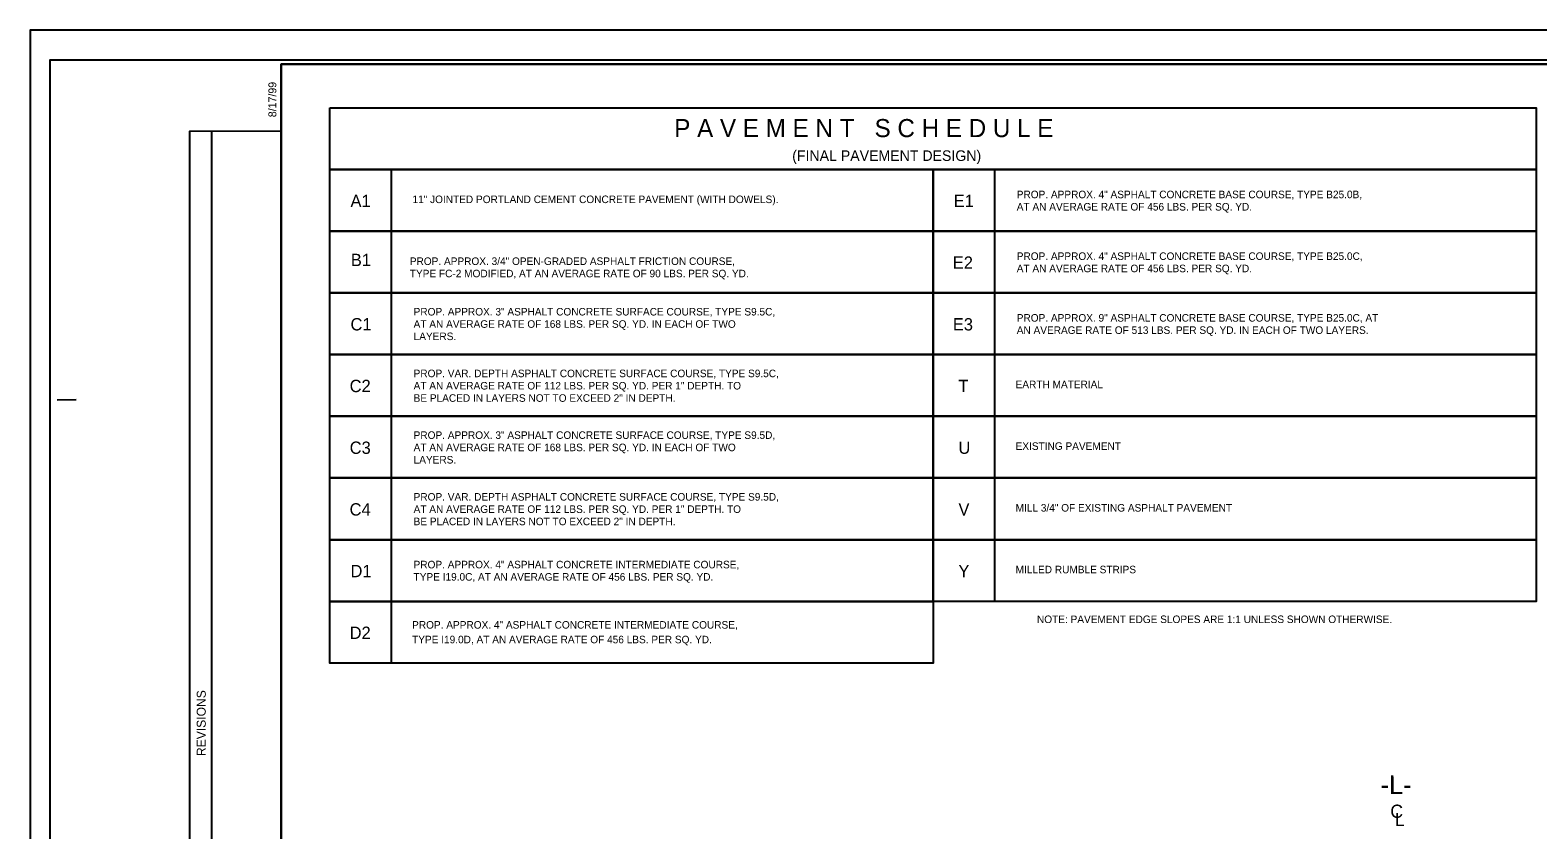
# Model space of a CAD drawing. Extents: x 2241081 to 2251104, y 658534 to 663427.
# Drawn here: x 2247636 to 2248635, y 662384 to 662914 of the extents above; entities that cross this region are included whole.
import ezdxf

# ---------------------------------------------------------------- set-up
doc = ezdxf.new("R2010")
doc.units = 0
for name, color, linetype in [('Prop Dimension Text', 7, 'Continuous'), ('Prop Pavement Schedule Description CELL', 7, 'Continuous'), ('Sheet Block Revision CELL', 7, 'Continuous'), ('Sheet Cutting Line CELL', 7, 'Continuous'), ('Sheet Plan CELL', 7, 'Continuous'), ('Sheet Plot Border Inside CELL', 7, 'Continuous'), ('Sheet Plot Border Outside CELL', 7, 'Continuous'), ('Typical Text Centerline CELL', 7, 'Continuous')]:
    doc.layers.add(name, color=color, linetype=linetype)

msp = doc.modelspace()

# ---------------------------------------------------------------- linework, layer by layer
at = {"layer": 'Prop Pavement Schedule Description CELL'}
msp.add_lwpolyline([(2247834.33, 662862.8), (2248634.35, 662862.8), (2248634.35, 662821.89), (2247834.33, 662821.89)], close=True, dxfattribs=at)
for points in [[(2247875.24, 662780.98), (2247834.33, 662780.98), (2247834.33, 662821.89), (2248234.33, 662821.89), (2248234.33, 662780.98), (2247875.24, 662780.98), (2247875.24, 662821.89)], [(2248275.24, 662780.96), (2248234.33, 662780.96), (2248234.33, 662821.86), (2248634.33, 662821.86), (2248634.33, 662780.96), (2248275.24, 662780.96), (2248275.24, 662821.86)], [(2247875.24, 662740.07), (2247834.33, 662740.07), (2247834.33, 662780.98), (2248234.33, 662780.98), (2248234.33, 662740.07), (2247875.24, 662740.07), (2247875.24, 662780.98)], [(2248275.24, 662740.05), (2248234.33, 662740.05), (2248234.33, 662780.96), (2248634.33, 662780.96), (2248634.33, 662740.05), (2248275.24, 662740.05), (2248275.24, 662780.96)], [(2247875.24, 662699.16), (2247834.33, 662699.16), (2247834.33, 662740.07), (2248234.33, 662740.07), (2248234.33, 662699.16), (2247875.24, 662699.16), (2247875.24, 662740.07)], [(2248275.24, 662699.14), (2248234.33, 662699.14), (2248234.33, 662740.05), (2248634.33, 662740.05), (2248634.33, 662699.14), (2248275.24, 662699.14), (2248275.24, 662740.05)], [(2247875.24, 662658.25), (2247834.33, 662658.25), (2247834.33, 662699.16), (2248234.33, 662699.16), (2248234.33, 662658.25), (2247875.24, 662658.25), (2247875.24, 662699.16)], [(2248275.24, 662658.24), (2248234.33, 662658.24), (2248234.33, 662699.15), (2248634.33, 662699.15), (2248634.33, 662658.24), (2248275.24, 662658.24), (2248275.24, 662699.15)], [(2247875.24, 662617.32), (2247834.33, 662617.32), (2247834.33, 662658.24), (2248234.33, 662658.24), (2248234.33, 662617.32), (2247875.24, 662617.32), (2247875.24, 662658.24)], [(2248275.24, 662617.33), (2248234.33, 662617.33), (2248234.33, 662658.24), (2248634.33, 662658.24), (2248634.33, 662617.33), (2248275.24, 662617.33), (2248275.24, 662658.24)], [(2247875.24, 662576.41), (2247834.33, 662576.41), (2247834.33, 662617.32), (2248234.33, 662617.32), (2248234.33, 662576.41), (2247875.24, 662576.41), (2247875.24, 662617.32)], [(2248275.24, 662576.42), (2248234.33, 662576.42), (2248234.33, 662617.33), (2248634.33, 662617.33), (2248634.33, 662576.42), (2248275.24, 662576.42), (2248275.24, 662617.33)], [(2247875.24, 662535.51), (2247834.33, 662535.51), (2247834.33, 662576.41), (2248234.33, 662576.41), (2248234.33, 662535.51), (2247875.24, 662535.51), (2247875.24, 662576.41)], [(2248275.24, 662535.51), (2248234.33, 662535.51), (2248234.33, 662576.41), (2248634.33, 662576.41), (2248634.33, 662535.51), (2248275.24, 662535.51), (2248275.24, 662576.41)], [(2247875.24, 662494.6), (2247834.33, 662494.6), (2247834.33, 662535.51), (2248234.33, 662535.51), (2248234.33, 662494.6), (2247875.24, 662494.6), (2247875.24, 662535.51)]]:
    msp.add_lwpolyline(points, dxfattribs=at)
at = {"layer": 'Sheet Block Revision CELL'}
msp.add_line((2247756.02, 662056.78), (2247756.01, 662847.42), dxfattribs=at)
msp.add_lwpolyline([(2247741.47, 662056.75), (2247741.47, 662847.4), (2247802.01, 662847.43), (2247802.01, 662056.78)], close=True, dxfattribs=at)
at = {"layer": 'Sheet Cutting Line CELL'}
for p, q in [((2249319.01, 662914.26), (2247635.51, 662914.27)), ((2247635.51, 662914.27), (2247635.51, 661819.27))]:
    msp.add_line(p, q, dxfattribs=at)
at = {"layer": 'Sheet Plan CELL'}
for p, q in [((2247802, 662891.78), (2247802, 662891.78)), ((2247653.5, 662669.25), (2247666.01, 662669.28))]:
    msp.add_line(p, q, dxfattribs=at)
for points in [[(2247802, 661841.78), (2247801.97, 662891.75), (2249101.96, 662891.79), (2249101.97, 662741.73), (2249302.01, 662741.71), (2249302.01, 661841.78)], [(2249302.03, 662891.78), (2247802, 662891.78), (2247802, 661841.78), (2249302.01, 661841.78)]]:
    msp.add_lwpolyline(points, close=True, dxfattribs=at)
at = {"layer": 'Sheet Plot Border Inside CELL'}
msp.add_lwpolyline([(2247648.51, 661839.27), (2249314.5, 661839.28), (2249314.51, 662894.26), (2247648.51, 662894.27)], close=True, dxfattribs=at)
at = {"layer": 'Sheet Plot Border Outside CELL'}
msp.add_lwpolyline([(2247635.51, 661819.27), (2249319.01, 661819.26), (2249319.01, 662914.26), (2247635.51, 662914.27)], close=True, dxfattribs=at)

# ---------------------------------------------------------------- texts
at = {"layer": 'Prop Dimension Text'}
msp.add_text('-L-', height=12.5, rotation=0.03489, dxfattribs=at).set_placement((2248531.19, 662407.7))
at = {"layer": 'Prop Pavement Schedule Description CELL'}
for s, height, p in [('P A V E M E N T   S C H E D U L E', 12, (2248062.67, 662843.33)), ('       (FINAL PAVEMENT DESIGN)', 7, (2248122.7, 662827.56)), ('A1', 8.167, (2247847.97, 662796.98)), ('E1', 8.167, (2248247.97, 662796.95)), ('PROP. APPROX. 4" ASPHALT CONCRETE BASE COURSE, TYPE B25.0B,', 5, (2248289.82, 662802.82)), ('11" JOINTED PORTLAND CEMENT CONCRETE PAVEMENT (WITH DOWELS).', 5, (2247889.06, 662799.6)), ('AT AN AVERAGE RATE OF 456 LBS. PER SQ. YD.', 5, (2248289.82, 662794.66)), ('PROP. APPROX. 4" ASPHALT CONCRETE BASE COURSE, TYPE B25.0C,', 5, (2248289.82, 662761.91)), ('E2', 8.167, (2248247.4, 662756.04)), ('AT AN AVERAGE RATE OF 456 LBS. PER SQ. YD.', 5, (2248289.82, 662753.76)), ('PROP. APPROX. 3" ASPHALT CONCRETE SURFACE COURSE, TYPE S9.5C, ', 5, (2247889.82, 662725.07)), ('C1', 8.167, (2247847.97, 662715.16)), ('AT AN AVERAGE RATE OF 168 LBS. PER SQ. YD. IN EACH OF TWO ', 5, (2247889.82, 662716.91)), ('LAYERS.', 5, (2247889.82, 662708.76)), ('T', 8.17, (2248251.14, 662674.24)), ('EARTH MATERIAL', 5, (2248289.06, 662676.86)), ('U', 8.17, (2248251.14, 662633.33)), ('EXISTING PAVEMENT', 5, (2248289.06, 662635.95)), ('V', 8.17, (2248251.17, 662592.42)), ('MILL 3/4" OF EXISTING ASPHALT PAVEMENT', 5, (2248289.06, 662595.04)), ('D1', 8.167, (2247847.97, 662551.51)), ('PROP. APPROX. 4" ASPHALT CONCRETE INTERMEDIATE COURSE,', 5, (2247889.78, 662557.41)), ('Y', 8.17, (2248251.14, 662551.51)), ('MILLED RUMBLE STRIPS', 5, (2248289.06, 662554.12)), ('TYPE I19.0C, AT AN AVERAGE RATE OF 456 LBS. PER SQ. YD.', 5, (2247889.78, 662549.26)), ('NOTE: PAVEMENT EDGE SLOPES ARE 1:1 UNLESS SHOWN OTHERWISE.', 5, (2248303.23, 662521.13))]:
    msp.add_text(s, height=height, dxfattribs=at).set_placement(p)
for s, height, p in [('B1', 8.167, (2247848.2, 662757.84)), (' TYPE FC-2 MODIFIED, AT AN AVERAGE RATE OF 90 LBS. PER SQ. YD.', 5, (2247885.44, 662750.41)), (' PROP. APPROX. 3/4" OPEN-GRADED ASPHALT FRICTION COURSE,', 5, (2247885.44, 662758.57)), ('PROP. APPROX. 9" ASPHALT CONCRETE BASE COURSE, TYPE B25.0C, AT', 5, (2248289.82, 662721)), ('E3', 8.167, (2248247.44, 662715.13)), ('AN AVERAGE RATE OF 513 LBS. PER SQ. YD. IN EACH OF TWO LAYERS.', 5, (2248289.82, 662712.85)), ('PROP. VAR. DEPTH ASPHALT CONCRETE SURFACE COURSE, TYPE S9.5C,', 5, (2247889.82, 662684.16)), ('C2', 8.167, (2247847.4, 662674.25)), ('AT AN AVERAGE RATE OF 112 LBS. PER SQ. YD. PER 1" DEPTH. TO', 5, (2247889.82, 662676)), ('BE PLACED IN LAYERS NOT TO EXCEED 2" IN DEPTH.', 5, (2247889.82, 662667.84)), ('PROP. APPROX. 3" ASPHALT CONCRETE SURFACE COURSE, TYPE S9.5D, ', 5, (2247889.82, 662643.24)), ('C3', 8.167, (2247847.44, 662633.32)), ('AT AN AVERAGE RATE OF 168 LBS. PER SQ. YD. IN EACH OF TWO ', 5, (2247889.82, 662635.08)), ('LAYERS.', 5, (2247889.82, 662626.92)), ('PROP. VAR. DEPTH ASPHALT CONCRETE SURFACE COURSE, TYPE S9.5D,', 5, (2247889.82, 662602.32)), ('C4', 8.167, (2247847.37, 662592.41)), ('AT AN AVERAGE RATE OF 112 LBS. PER SQ. YD. PER 1" DEPTH. TO', 5, (2247889.82, 662594.16)), ('BE PLACED IN LAYERS NOT TO EXCEED 2" IN DEPTH.', 5, (2247889.82, 662586.01)), ('D2', 8.167, (2247847.4, 662510.59)), ('PROP. APPROX. 4" ASPHALT CONCRETE INTERMEDIATE COURSE,', 5, (2247888.82, 662517.44)), ('TYPE I19.0D, AT AN AVERAGE RATE OF 456 LBS. PER SQ. YD.', 5, (2247888.82, 662507.71))]:
    msp.add_text(s, height=height, rotation=359.99993, dxfattribs=at).set_placement(p)
at = {"layer": 'Sheet Block Revision CELL'}
msp.add_text('REVISIONS', height=6, rotation=89.99993, dxfattribs=at).set_placement((2247751.97, 662432.93))
at = {"layer": 'Sheet Plan CELL'}
msp.add_text('8/17/99', height=5.25, rotation=89.99994, dxfattribs=at).set_placement((2247798.77, 662856.55))
at = {"layer": 'Typical Text Centerline CELL'}
for s, rotation, p in [('C', 0.03489, (2248537.57, 662391.96)), ('L', 359.98179, (2248540.6, 662386.46))]:
    msp.add_text(s, height=8.76, rotation=rotation, dxfattribs=at).set_placement(p)

doc.saveas('drawing.dxf')
